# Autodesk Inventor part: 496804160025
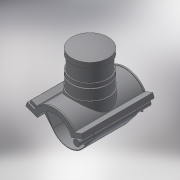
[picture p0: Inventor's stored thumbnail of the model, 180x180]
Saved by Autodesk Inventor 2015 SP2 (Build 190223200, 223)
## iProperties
Created: 2017-07
Part Number: 496804160025
Material: Generic
Description: PLASSON BALLOON SADDLE 160-2.1/2
Document SubType Name: Modeling
Designer: KIM
Density: 1 g/cm^3
Appearance: Default
Author: KIM
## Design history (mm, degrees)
derived "496804.ipt"
feature "Solid1::496804.ipt"
feature "Solid2::496804.ipt"
tag "TaggingFeature1"
body "Solid1"
body "Solid2"
other parameters: "d1" = 184, "d4" = 176, "d5" = 0, "d40" = 95.68, "d96" = 187.68, "d97" = 3.52, "d98" = 0, "d120" = 120 deg, "d121" = 24.228, "d122" = 30 deg, "d123" = 368, "d124" = 110.4, "d126" = 0, "d143" = 164.8, "d145" = 18.46154, "d149" = 2.4, "d150" = 20.30769, "d153" = 176, "d154" = 0, "d159" = 4.8, "d161" = 2.4, "d162" = 105.6, "d163" = 0, "d168" = 86.79245, "d170" = 2.4, "d172" = 0, "d173" = 1, "d176" = 30 deg, "d177" = 12.8, "d180" = 0, "d185" = 57.2, "d186" = 57.2, "d187" = 92, "d188" = 7.2, "d190" = 0, "d191" = 147.2, "d193" = 4.8, "d194" = 4.4, "d195" = 90 deg, "d197" = 0, "d199" = 0, "d200" = 105, "d201" = 1, "d203" = 94.5, "d204" = 97.65, "d205" = 85.5, "d206" = 1.8, "d207" = 52.5, "d208" = 42, "d209" = 84, "d210" = 15.75, "d214" = 184, "d216" = 0, "d217" = 88, "d218" = 35, "d219" = 24, "d220" = 15.98, "d221" = 15 deg, "d223" = 6.92058, "d224" = 3.46029, "d226" = 0, "d227" = -17.6, "d228" = 2.4, "d229" = 35.2, "B_" = 176, "H_" = 105, "L_" = 176, "d_t" = 6, "d148" = 2.4, "d160" = 2.4, "d169" = 2.4, "d192" = 4.8, "d222" = 8.65072
